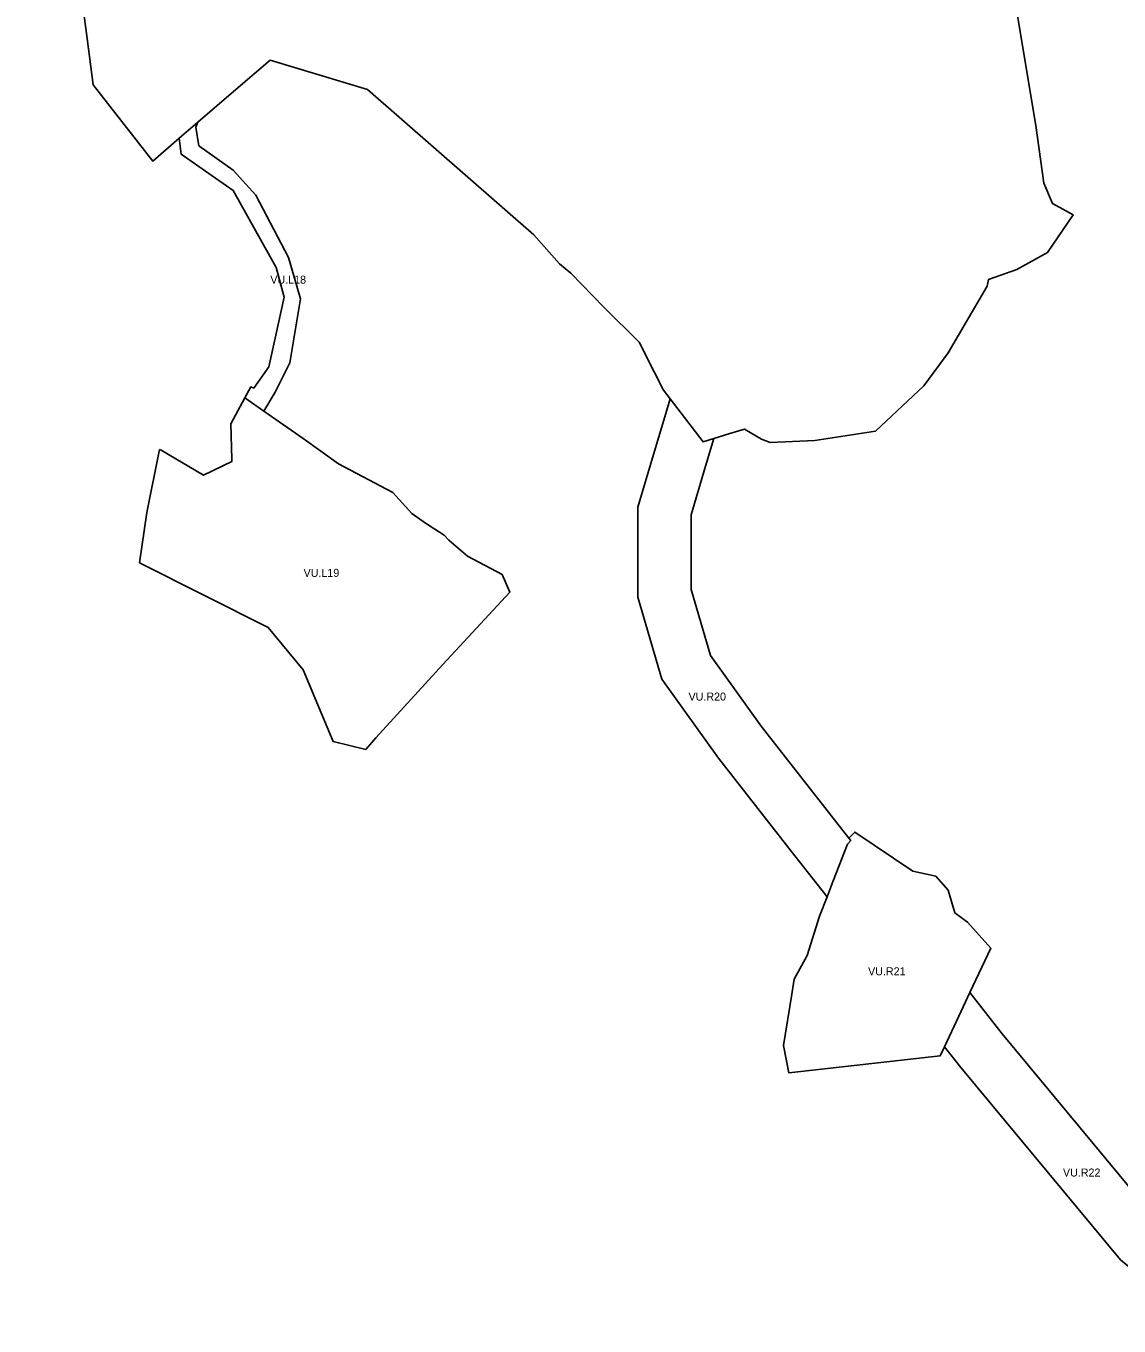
# Model space of a CAD drawing. Extents: x -439083 to -433688, y -1130252 to -1121189.
# Drawn here: x -436560 to -434920, y -1129438 to -1127489 of the extents above; entities that cross this region are included whole.
import ezdxf

# ---------------------------------------------------------------- set-up
doc = ezdxf.new("R2010")
doc.units = 0
doc.layers.add('Vrstva 28', color=7, linetype='Continuous')
doc.layers.add('Vrstva 31', color=7, linetype='Continuous')

msp = doc.modelspace()

# ---------------------------------------------------------------- linework, layer by layer
at = {"layer": 'Vrstva 28'}
for p, q in [((-436329.7, -1127657.1), (-436301.6, -1127633)), ((-436301.6, -1127633), (-436329.7, -1127657.1)), ((-436231.5, -1128046.6), (-436252.5, -1128085.2)), ((-436202.8, -1128066.5), (-436231.5, -1128046.6)), ((-436231.5, -1128046.6), (-436202.8, -1128066.5)), ((-436143.6, -1128107.6), (-436202.8, -1128066.5)), ((-435543.9, -1128112.5), (-435527.7, -1128107.5)), ((-435348.4, -1128770.6), (-435327, -1128715.9)), ((-435327, -1128715.9), (-435322.1, -1128710.3)), ((-435324.9, -1128706.8), (-435322.1, -1128710.3)), ((-435322.1, -1128710.3), (-435324.9, -1128706.8)), ((-435348.4, -1128770.6), (-435357.8, -1128794.5)), ((-435357.8, -1128794.5), (-435348.4, -1128770.6)), ((-435160, -1128973.7), (-435143.5, -1128938.4)), ((-435143.5, -1128938.4), (-435160, -1128973.7)), ((-435181.5, -1129019.6), (-435160, -1128973.7)), ((-435160, -1128973.7), (-435181.5, -1129019.6))]:
    msp.add_line(p, q, dxfattribs=at)
for points in [[(-436557.2, -1127039.4), (-436559.7, -1127094.2), (-436550.5, -1127132.4), (-436511.6, -1127176.5), (-436491.6, -1127327.6), (-436489.7, -1127342), (-436467.8, -1127507.6), (-436458.8, -1127576.8), (-436369.4, -1127691.4), (-436329.7, -1127657.1)], [(-435527.7, -1128107.5), (-435503.6, -1128100.1), (-435481.7, -1128093.4), (-435456, -1128108.2), (-435443.3, -1128113.4), (-435375.9, -1128110.2), (-435285.1, -1128096.6), (-435212.6, -1128028.6), (-435176.3, -1127978.7), (-435117.3, -1127878.9), (-435115.6, -1127869.2), (-435072.9, -1127853.8), (-435027.1, -1127828.4), (-434988.3, -1127772), (-435019.3, -1127755.1), (-435032.7, -1127724.7), (-435044.7, -1127638), (-435091.3, -1127356), (-435144.1, -1127350.3), (-435172.3, -1127341.9), (-435193.2, -1127332.3), (-435193.2, -1127332.3)], [(-436301.6, -1127633), (-436244.8, -1127584), (-436193.5, -1127539.8), (-436047.1, -1127584.1), (-435797.7, -1127801.8), (-435759.2, -1127845.4), (-435742, -1127859.4), (-435692.7, -1127910.2), (-435639.8, -1127963.1), (-435617.1, -1128007.6), (-435603.1, -1128035), (-435593.4, -1128047.7), (-435543.9, -1128112.5)], [(-436202.8, -1128066.5), (-436186, -1128037.9), (-436164, -1127993.8), (-436147.9, -1127898.1), (-436165.7, -1127835.8), (-436214.8, -1127742.5), (-436248.7, -1127705.2), (-436300.4, -1127668.3), (-436304.6, -1127640.7), (-436301.6, -1127633)], [(-436329.7, -1127657.1), (-436326.7, -1127681.2), (-436248.7, -1127735.4), (-436184.3, -1127850.8), (-436172.4, -1127895.2), (-436185, -1127952.2), (-436195.5, -1128000), (-436217.8, -1128031.8)], [(-436217.8, -1128031.8), (-436222.3, -1128029.7), (-436231.5, -1128046.6)], [(-435593.4, -1128047.7), (-435604.4, -1128084.8), (-435616.7, -1128126.2), (-435641.6, -1128210.4), (-435641.6, -1128345.5), (-435605.8, -1128468.3), (-435520.6, -1128586.6), (-435405.9, -1128733.1), (-435357.8, -1128794.5)], [(-435527.7, -1128107.5), (-435543.9, -1128112.5), (-435593.4, -1128047.7)], [(-436252.5, -1128085.2), (-436250.9, -1128138.5), (-436250.8, -1128141.7), (-436293.5, -1128162.4), (-436357.1, -1128124.7), (-436359.2, -1128123.9), (-436378.3, -1128218.2), (-436389.3, -1128293.7), (-436196.1, -1128390.6), (-436143.6, -1128454.2), (-436098.7, -1128561.9), (-436050, -1128573.7), (-436034.9, -1128556.2), (-435934.2, -1128446.2), (-435833.5, -1128337.7), (-435845, -1128311.6), (-435897.2, -1128284), (-435925.4, -1128260.1), (-435932.3, -1128252.4), (-435960.4, -1128234.4), (-435980.9, -1128219.9), (-436009.4, -1128188.4), (-436090.9, -1128145.6), (-436143.6, -1128107.6)], [(-435324.9, -1128706.8), (-435342.9, -1128683.8), (-435456.6, -1128538.6), (-435532.8, -1128432.7), (-435561.6, -1128334), (-435561.6, -1128222.1), (-435540, -1128149), (-435527.7, -1128107.5)], [(-435143.5, -1128938.4), (-435112.2, -1128871.6), (-435147.3, -1128832.9), (-435165.9, -1128818.5), (-435176.1, -1128784.7), (-435194.6, -1128763.9), (-435228.9, -1128756), (-435316.1, -1128697.7), (-435324.9, -1128706.8)], [(-435322.1, -1128710.3), (-435327, -1128715.9), (-435348.4, -1128770.6)], [(-435357.8, -1128794.5), (-435369.2, -1128823.7), (-435387.7, -1128882.9), (-435407, -1128918.3), (-435410.6, -1128940.9), (-435422.9, -1129017.8), (-435414.9, -1129058.7), (-435187.9, -1129033.1), (-435181.5, -1129019.6)], [(-434815.5, -1129319.6), (-434861, -1129282.1), (-435095.1, -1129000.3), (-435143.5, -1128938.4)], [(-435181.5, -1129019.6), (-435157.3, -1129050.5), (-434917.7, -1129339), (-434866.4, -1129381.3), (-434816.5, -1129422.6), (-434797.4, -1129438.3)]]:
    msp.add_lwpolyline(points, dxfattribs=at)

# ---------------------------------------------------------------- texts
at = {"layer": 'Vrstva 31'}
for s, p in [('VU.L18', (-436193, -1127875.2)), ('VU.L19', (-436143.2, -1128314.9)), ('VU.R20', (-435565.6, -1128500.4)), ('VU.R21', (-435296.2, -1128912.4)), ('VU.R22', (-435003.8, -1129214.2))]:
    msp.add_text(s, height=12, dxfattribs=at).set_placement(p)

doc.saveas('drawing.dxf')
